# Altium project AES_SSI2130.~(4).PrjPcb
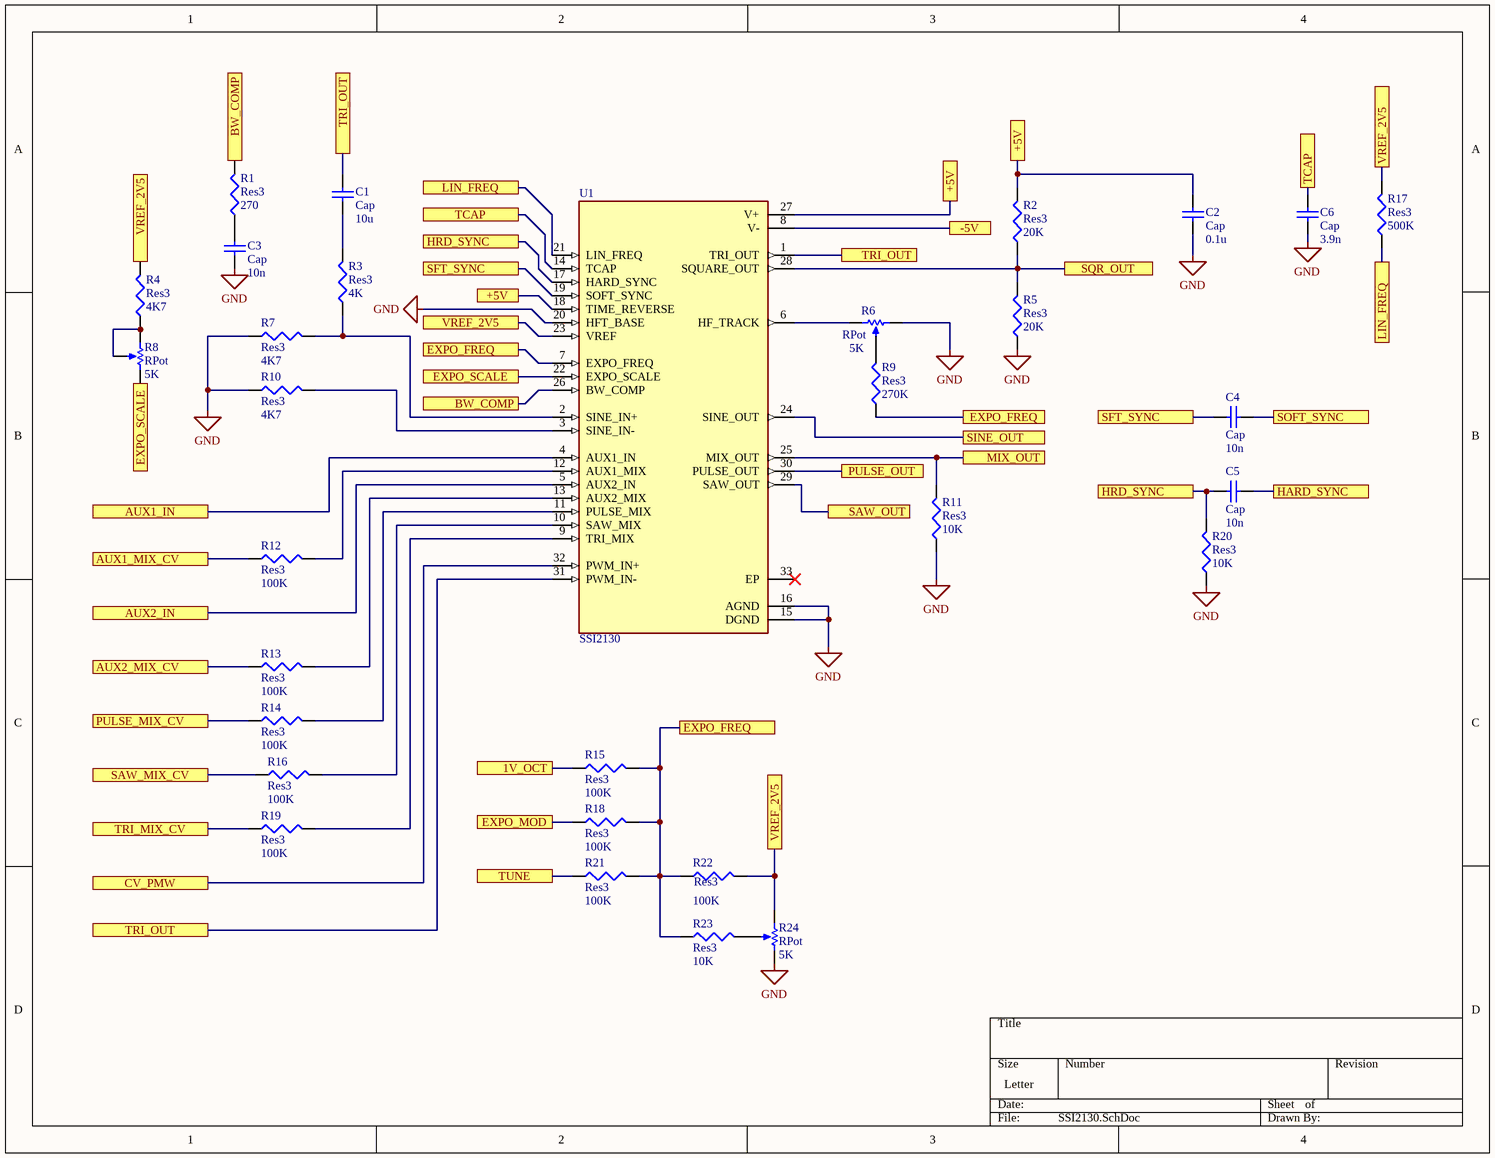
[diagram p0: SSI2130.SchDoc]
2 sheets, 39 parts. Net scope: flat (ports and power ports of the same name join across sheets).
Sheets:
  SSI2130.SchDoc
  power.SchDoc

## Sheet SSI2130.SchDoc
size Letter

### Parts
C1  Cap  value 10u  [RAD-0.3]
C2  Cap  value 0.1u  [RAD-0.3]
C3  Cap  value 10n  [RAD-0.3]
C4  Cap  value 10n  [RAD-0.3]
C5  Cap  value 10n  [RAD-0.3]
C6  Cap  value 3.9n  [RAD-0.3]
R1  Res3  value 270  [J1-0603]
R2  Res3  value 20K  [J1-0603]
R3  Res3  value 4K  [J1-0603]
R4  Res3  value 4K7  [J1-0603]
R5  Res3  value 20K  [J1-0603]
R6  RPot  value 5K  [VR5]
R7  Res3  value 4K7  [J1-0603]
R8  RPot  value 5K  [VR5]
R9  Res3  value 270K  [J1-0603]
R10  Res3  value 4K7  [J1-0603]
R11  Res3  value 10K  [J1-0603]
R12  Res3  value 100K  [J1-0603]
R13  Res3  value 100K  [J1-0603]
R14  Res3  value 100K  [J1-0603]
R15  Res3  value 100K  [J1-0603]
R16  Res3  value 100K  [J1-0603]
R17  Res3  value 500K  [J1-0603]
R18  Res3  value 100K  [J1-0603]
R19  Res3  value 100K  [J1-0603]
R20  Res3  value 10K  [J1-0603]
R21  Res3  value 100K  [J1-0603]
R22  Res3  value 100K  [J1-0603]
R23  Res3  value 10K  [J1-0603]
R24  RPot  value 5K  [VR5]
U1  SSI2130  [QFN40P400X400X90-33N]

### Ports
1V_OCT, +5V, -5V, AUX1_IN, AUX1_MIX_CV, AUX2_IN, AUX2_MIX_CV, BW_COMP, CV_PMW, EXPO_FREQ, EXPO_MOD, EXPO_SCALE, HARD_SYNC, HRD_SYNC, LIN_FREQ, MIX_OUT, PULSE_MIX_CV, PULSE_OUT, SAW_MIX_CV, SAW_OUT, SFT_SYNC, SINE_OUT, SOFT_SYNC, SQR_OUT, TCAP, TRI_MIX_CV, TRI_OUT, TUNE, VREF_2V5

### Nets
GND: C2.1 C3.1 C6.1 R5.1 R6.2(BOT) R7.1 R10.1 R11.1 R20.1 R24.2(BOT) U1.15(DGND) U1.16(AGND) U1.20(HFT_BASE)
NetC1_1: C1.1 R3.2
NetC1_2: C1.2 U1.1(TRI_OUT) U1.31(PWM_IN-) ; port TRI_OUT
NetC2_2: C2.2 R2.2 U1.18(TIME_REVERSE) U1.27(V+) ; port +5V
NetC3_2: C3.2 R1.1
NetC4_1: C4.1 U1.19(SOFT_SYNC) ; port SFT_SYNC
NetC4_2: C4.2 ; port SOFT_SYNC
NetC5_1: C5.1 R20.2 U1.17(HARD_SYNC) ; port HRD_SYNC
NetC5_2: C5.2 ; port HARD_SYNC
NetC6_2: C6.2 U1.14(TCAP) ; port TCAP
NetC7_2: U1.8(V-) ; port -5V
NetR1_2: R1.2 U1.26(BW_COMP) ; port BW_COMP
NetR2_1: R2.1 R5.2 U1.28(SQUARE_OUT) ; port SQR_OUT
NetR3_1: R3.1 R7.2 U1.2(SINE_IN+)
NetR4_1: R4.1 R8.1(TOP) R8.3(TAP)
NetR4_2: R4.2 R17.2 R22.2 R24.1(TOP) U1.23(VREF) ; port VREF_2V5
NetR6_1: R6.1(TOP) U1.6(HF_TRACK)
NetR6_3: R6.3(TAP) R9.2
NetR8_2: R8.2(BOT) U1.22(EXPO_SCALE) ; port EXPO_SCALE
NetR9_1: R9.1 R15.2 R18.2 R21.2 R22.1 R23.1 U1.7(EXPO_FREQ) ; port EXPO_FREQ
NetR10_2: R10.2 U1.3(SINE_IN-)
NetR11_2: R11.2 U1.25(MIX_OUT) ; port MIX_OUT
NetR12_1: R12.1 ; port AUX1_MIX_CV
NetR12_2: R12.2 U1.12(AUX1_MIX)
NetR13_1: R13.1 ; port AUX2_MIX_CV
NetR13_2: R13.2 U1.13(AUX2_MIX)
NetR14_1: R14.1 ; port PULSE_MIX_CV
NetR14_2: R14.2 U1.11(PULSE_MIX)
NetR15_1: R15.1 ; port 1V_OCT
NetR16_1: R16.1 ; port SAW_MIX_CV
NetR16_2: R16.2 U1.10(SAW_MIX)
NetR17_1: R17.1 U1.21(LIN_FREQ) ; port LIN_FREQ
NetR18_1: R18.1 ; port EXPO_MOD
NetR19_1: R19.1 ; port TRI_MIX_CV
NetR19_2: R19.2 U1.9(TRI_MIX)
NetR21_1: R21.1 ; port TUNE
NetR23_2: R23.2 R24.3(TAP)
NetU1_4: U1.4(AUX1_IN) ; port AUX1_IN
NetU1_5: U1.5(AUX2_IN) ; port AUX2_IN
NetU1_24: U1.24(SINE_OUT) ; port SINE_OUT
NetU1_29: U1.29(SAW_OUT) ; port SAW_OUT
NetU1_30: U1.30(PULSE_OUT) ; port PULSE_OUT
NetU1_32: U1.32(PWM_IN+) ; port CV_PMW

Not connected (* = marked no-connect by the designer): U1 33(EP)*

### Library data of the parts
C1-C6 = Cap: Capacitor
R1-R5 R7 R9-R23 = Res3: Resistor
R6 R8 R24 = RPot: Potentiometer; Sim Note: Enter the Resistance value and the set point into parameter fields.; Set Position: 0.5
U1 = SSI2130: Voltage controlled oscillator subsystem for high-performance electronic musical instruments; MF: Sound Semiconductor

## Sheet power.SchDoc
size Letter
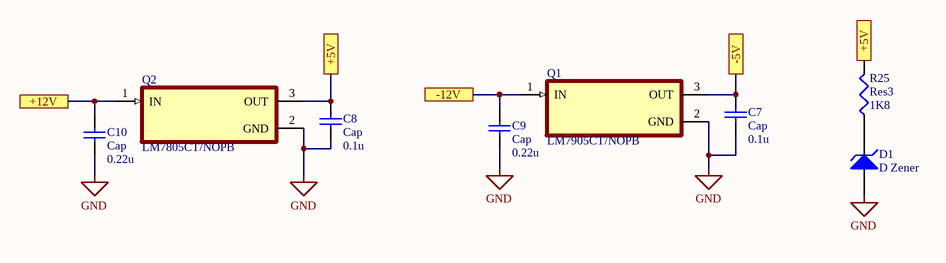
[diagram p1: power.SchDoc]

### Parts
C7  Cap  value 0.1u  [RAD-0.3]
C8  Cap  value 0.1u  [RAD-0.3]
C9  Cap  value 0.22u  [RAD-0.3]
C10  Cap  value 0.22u  [RAD-0.3]
D1  D Zener  [DIODE-0.7]
Q1  LM7905CT/NOPB  [TO254P1054X470X1955-3]
Q2  LM7805CT/NOPB  [TO254P1054X470X1955-3]
R25  Res3  value 1K8  [J1-0603]

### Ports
+5V, +12V, -5V, -12V

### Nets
GND: C7.1 C8.1 C9.1 C10.1 D1.1(A) Q1.2(GND) Q2.2(GND)
NetC2_2: C8.2 Q2.3(OUT) R25.2 ; port +5V
NetC7_2: C7.2 Q1.3(OUT) ; port -5V
NetC9_2: C9.2 Q1.1(IN) ; port -12V
NetC10_2: C10.2 Q2.1(IN) ; port +12V
NetD1_2: D1.2(K) R25.1

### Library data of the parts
C7-C10 = Cap: Capacitor
D1 = D Zener: Zener Diode
Q1 Q2 = LM7805CT/NOPB: 1.5-A, 30-V, linear voltage regulator 3-TO-220 0 to 125; MF: Texas Instruments
R25 = Res3: Resistor

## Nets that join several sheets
GND: SSI2130 (13 pins), power (7 pins)
NetC2_2: SSI2130 (C2.2 R2.2 U1.18 U1.27), power (C8.2 Q2.3 R25.2)
NetC7_2: SSI2130 (U1.8), power (C7.2 Q1.3)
